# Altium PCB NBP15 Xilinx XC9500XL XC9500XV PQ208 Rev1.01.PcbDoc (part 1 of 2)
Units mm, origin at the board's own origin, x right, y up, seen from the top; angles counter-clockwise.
Board outline 69 x 80.99 mm, 2 copper layers (Top Layer, Bottom Layer); 37 components, 186 nets, 485 pads, 89 vias.
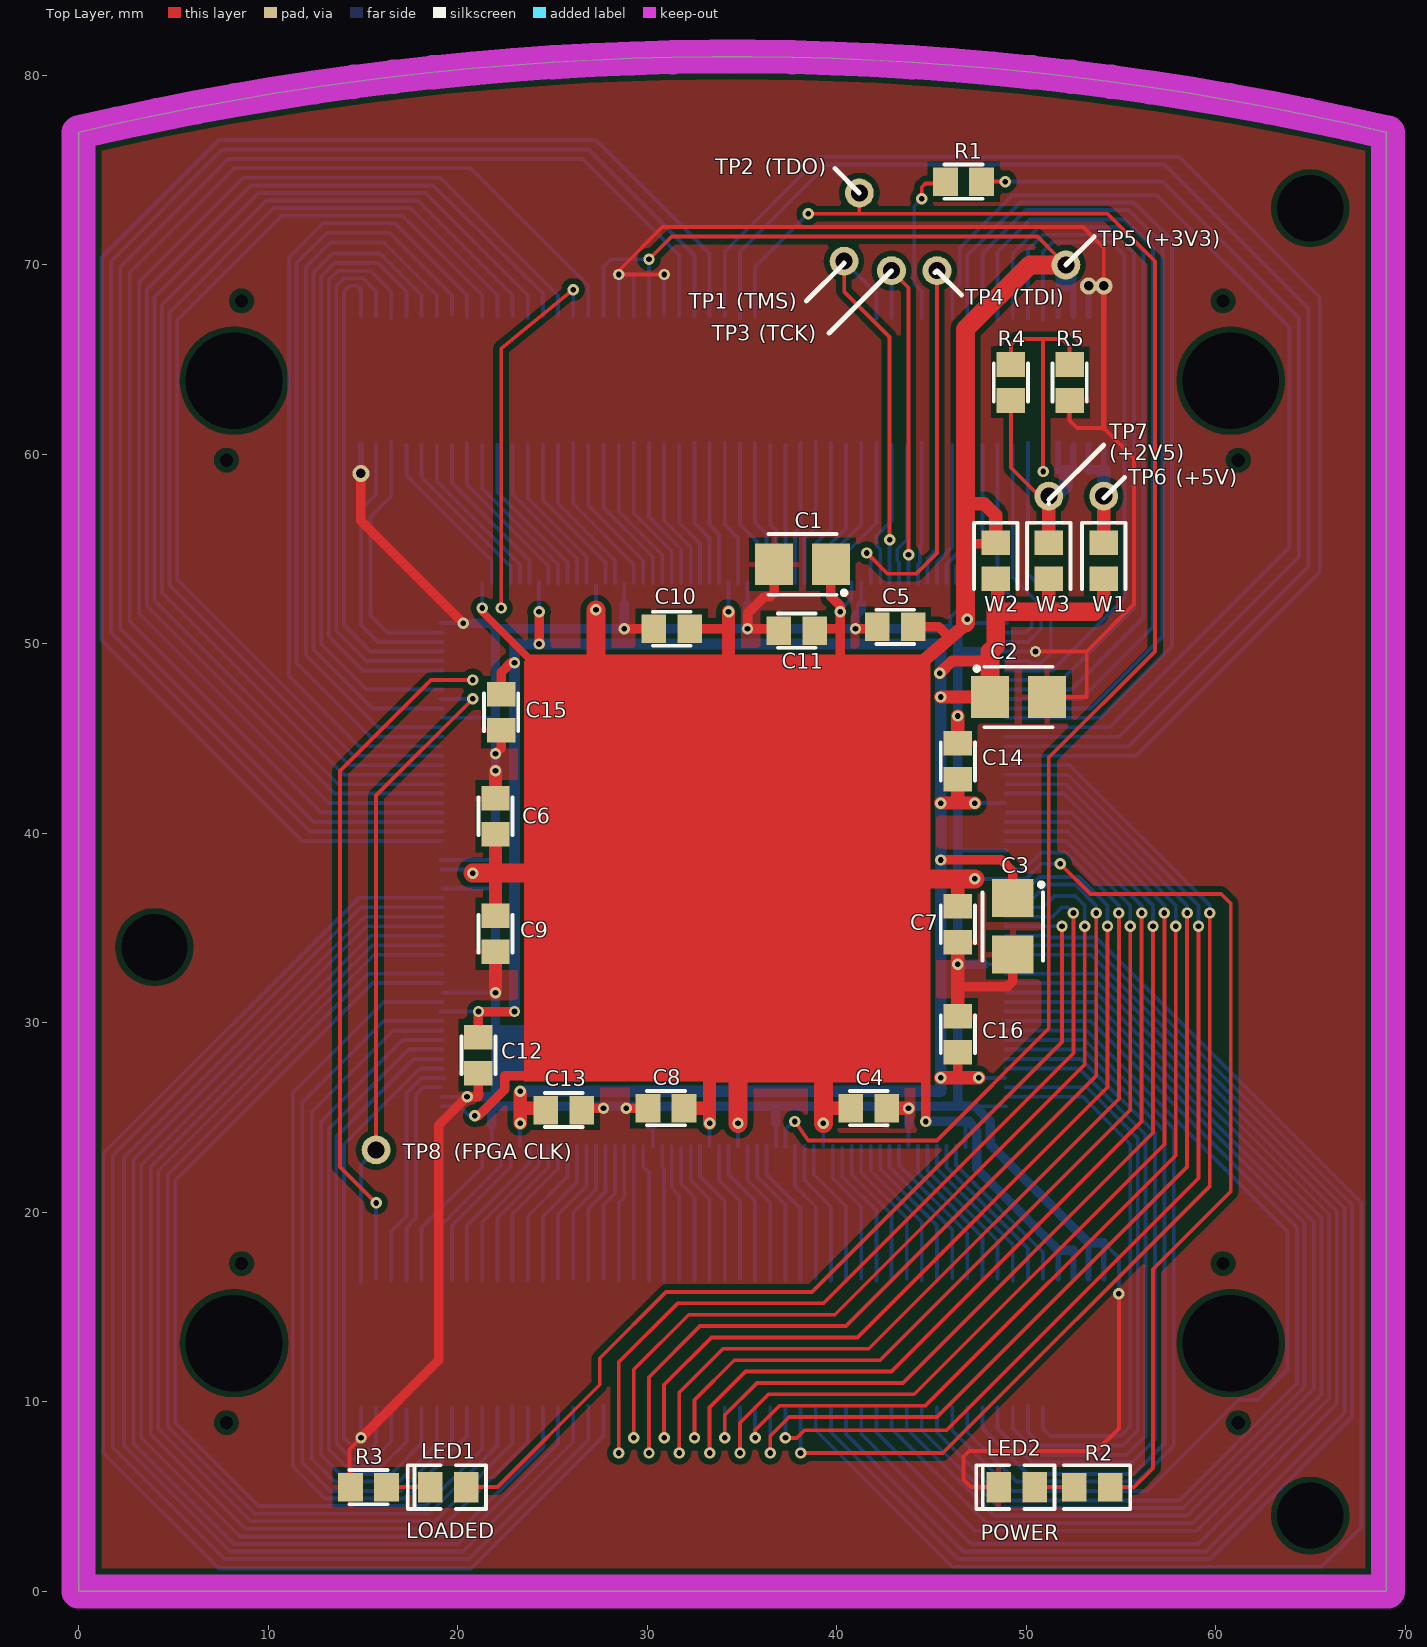
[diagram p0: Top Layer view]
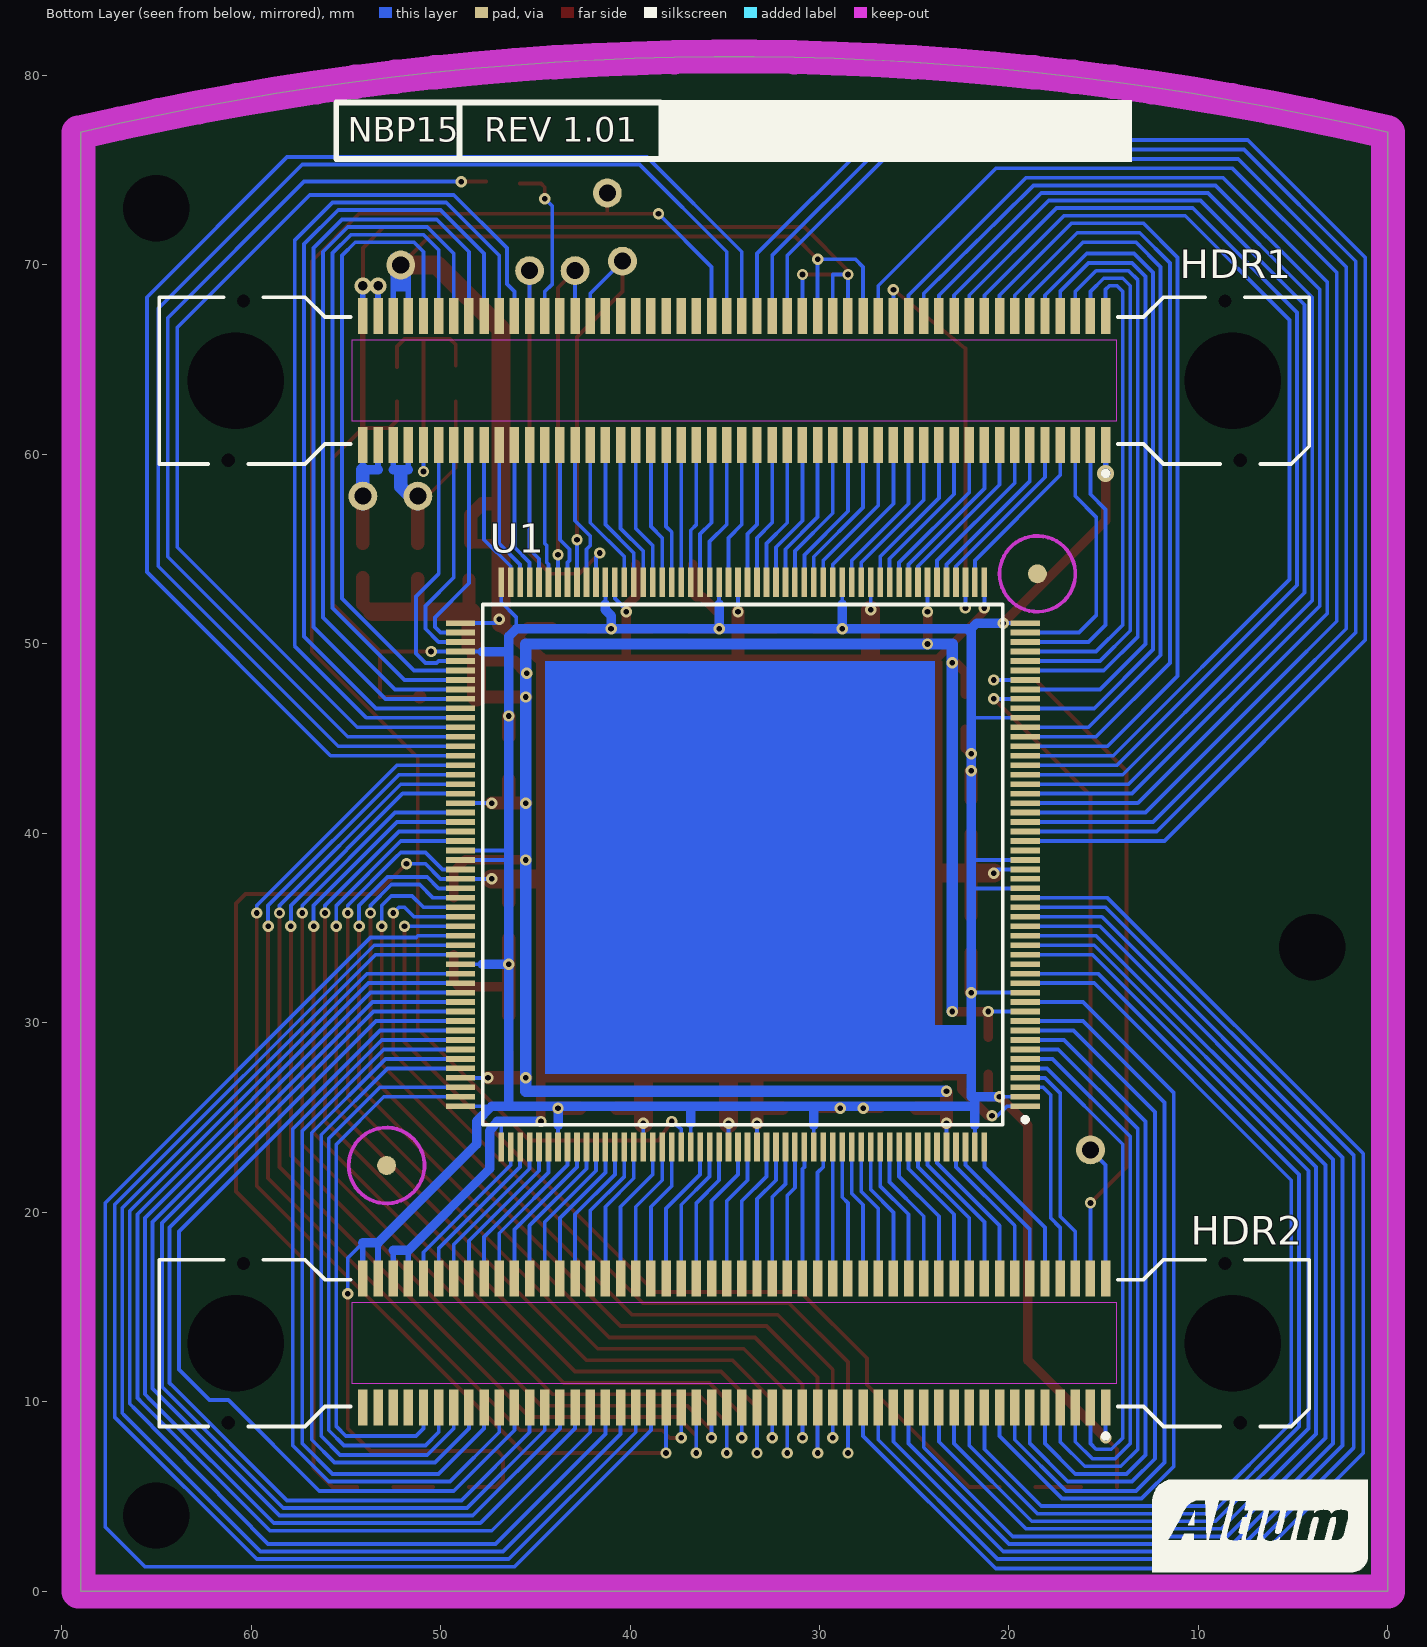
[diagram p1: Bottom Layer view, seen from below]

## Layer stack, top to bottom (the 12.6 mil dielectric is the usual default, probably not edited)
Top Layer: signal copper 0.0356
Dielectric: core 0.32, FR-4, Dk 4.8
Bottom Layer: signal copper 0.0356

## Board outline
0,0 0.001,77 cw(c34.5,-69.801) 69,77 69,0

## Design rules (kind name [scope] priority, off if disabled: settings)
AcuteAngle [All] p1 off: minimum=4.50000000000000E+0001
Clearance Clearance_Polygons [InPolygon] p1: gap=0.3
Clearance [All] p2: gap=0.2
ComponentClearance [All] p1: gap=0.2 collisioncheckmode=3 verticalgap=0.254 showdistances=FALSE
FabricationTestPointUsage TestPointUsage [All] p1 off: valid=0 allowmultiple=FALSE
FabricationTestpoint Testpoint [All] p1 off: side=3 testpointundercomponent=TRUE minsize=1.016 maxsize=2.54 preferedsize=1.524 minholesize=0 maxholesize=1.016 preferedholesize=0.813 testpointgrid=0.025 allowsidetop=TRUE allowsidebottom=TRUE usegrid=TRUE gridtolerance=0
HoleSize [All] p1: absolutevalues=TRUE maxlimit=5.2 minlimit=0.25 maxpercent=80.000 minpercent=20.000
MaximumViaCount [All] p1 off: limit=2
PlaneClearance [All] p1: clearance=0.45
PlaneConnect [All] p1: planeconnectstyle=Direct reliefexpansion=0.5 reliefentries=4 reliefconductorwidth=0.25 reliefairgap=0.25
PolygonConnect [All] p1: connectstyle=Relief reliefconductorwidth=0.3 reliefentries=4 polygonreliefangle="90 Angle"
RoomDefinition BOC_XC95288_PQ208 [InComponentClass('BOC_XC95288_PQ208')] p1 off: confinementstyle=ConfineIn formatcopy=TRUE lockcomponents=FALSE outline 3.6,3.7 65.2,3.7 65.2,75.8 3.6,75.8
RoutingVias [All] p1: holewidth=0.3 width=0.6 viastyle="Through Hole" minholewidth=0.3 minwidth=0.6 maxholewidth=0.5 maxwidth=1.4
SMDNeckDown [All] p1: percent=80.000
SilkscreenOverComponentPads [All] p1: minsilkscreentomaskgap=0.254
SolderMaskExpansion SolderMaskExpansion_Vias [IsVia] p1: expansion=-0.15
SolderMaskExpansion [All] p2: expansion=0.15
Width [All] p1: maxlimit=1.4 minlimit=0.2 preferedwidth=1 bottomlayer_prefwidth=0.2
21 further rules are at their usual default settings.

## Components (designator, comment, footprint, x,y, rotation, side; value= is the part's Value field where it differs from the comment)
C1 "10uF" MCCT-B 38.2,54.2 r180 top
C2 "10uF" MCCT-B 49.6,47.2 r0 top
C3 "10uF" MCCT-B 49.3,35.1 r270 top
C4 "0.1uF" CC2012-0805 41.7,25.5 r0 top
C5 "0.1uF" CC2012-0805 43.1,50.9 r180 top
C6 "0.1uF" CC2012-0805 22,40.9 r90 top
C7 "0.1uF" CC2012-0805 46.4,35.2 r270 top
C8 "0.1uF" CC2012-0805 31,25.5 r180 top
C9 "0.1uF" CC2012-0805 22,34.7 r270 top
C10 "0.1uF" CC2012-0805 31.3,50.8 r180 top
C11 "0.1uF" CC2012-0805 37.9,50.7 r180 top
C12 "0.1uF" CC2012-0805 21.1,28.3 r270 top
C13 "0.1uF" CC2012-0805 25.6,25.4 r0 top
C14 "0.1uF" CC2012-0805 46.4,43.8 r90 top
C15 "0.1uF" CC2012-0805 22.3,46.4 r270 top
C16 "0.1uF" CC2012-0805 46.4,29.4 r90 top
HDR1 "54075-1009-HD1" 54075 34.5,63.9 r0 bottom locked
HDR2 "54075-1009-HD2" 54075 34.5,13.1 r0 bottom locked
LED1 "HSMG-C170" "SMD _LED" 19.5,5.5 r0 top locked
LED2 "HSMH-C170" "SMD _LED" 49.5,5.5 r0 top locked
R1 "100R" CC2012-0805 46.7,74.4 r0 top
R2 "270R" CC2012-0805 53.5,5.5 r180 top locked
R3 "270R" CC2012-0805 15.3,5.5 r0 top
R4 "82R/1%" CC2012-0805 49.2,63.8 r90 top
R5 "680R/1%" CC2012-0805 52.3,63.8 r270 top
TP1 "TestPin" TestPin 40.4,70.2 r90 top
TP2 "TestPin" TestPin 41.2,73.8 r90 top
TP3 "TestPin" TestPin 42.9,69.7 r90 top
TP4 "TestPin" TestPin 45.3,69.7 r90 top
TP5 "TestPin" TestPin 52.1,70 r90 top
TP6 "TestPin" TestPin 54.1,57.8 r90 top
TP7 "TestPin" TestPin 51.2,57.8 r90 top
TP8 "TestPin" TestPin 15.7,23.3 r90 top
U1 "XC95288XL-10PQ208C" PQ208 34.05,38.35 r0 bottom locked
W1 "Jumper" CC2012-0805 54.1,54.4 r270 top
W2 "Jumper" CC2012-0805 48.4,54.4 r270 top
W3 "Jumper" CC2012-0805 51.2,54.4 r270 top

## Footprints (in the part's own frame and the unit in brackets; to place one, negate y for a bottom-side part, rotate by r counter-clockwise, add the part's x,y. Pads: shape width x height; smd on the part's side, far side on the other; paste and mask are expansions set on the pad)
54075 [mm] "Connector; Docking Station, Receptacle; 100 Position; Vertical"
  rect 0.5x1.9 smd: 1(-19.6,3.4) 2(-19.6,-3.4) 3(-18.8,3.4) 4(-18.8,-3.4) 5(-18,3.4) 6(-18,-3.4) 7(-17.2,3.4) 8(-17.2,-3.4) 9(-16.4,3.4) 10(-16.4,-3.4) 11(-15.6,3.4) 12(-15.6,-3.4) 13(-14.8,3.4) 14(-14.8,-3.4) 15(-14,3.4) 16(-14,-3.4) 17(-13.2,3.4) 18(-13.2,-3.4) 19(-12.4,3.4) 20(-12.4,-3.4) 21(-11.6,3.4) 22(-11.6,-3.4) 23(-10.8,3.4) 24(-10.8,-3.4) 25(-10,3.4) 26(-10,-3.4) 27(-9.2,3.4) 28(-9.2,-3.4) 29(-8.4,3.4) 30(-8.4,-3.4) 31(-7.6,3.4) 32(-7.6,-3.4) 33(-6.8,3.4) 34(-6.8,-3.4) 35(-6,3.4) 36(-6,-3.4) 37(-5.2,3.4) 38(-5.2,-3.4) 39(-4.4,3.4) 40(-4.4,-3.4) 41(-3.6,3.4) 42(-3.6,-3.4) 43(-2.8,3.4) 44(-2.8,-3.4) 45(-2,3.4) 46(-2,-3.4) 47(-1.2,3.4) 48(-1.2,-3.4) 49(-0.4,3.4) 50(-0.4,-3.4) 51(0.4,3.4) 52(0.4,-3.4) 53(1.2,3.4) 54(1.2,-3.4) 55(2,3.4) 56(2,-3.4) 57(2.8,3.4) 58(2.8,-3.4) 59(3.6,3.4) 60(3.6,-3.4) 61(4.4,3.4) 62(4.4,-3.4) 63(5.2,3.4) 64(5.2,-3.4) 65(6,3.4) 66(6,-3.4) 67(6.8,3.4) 68(6.8,-3.4) 69(7.6,3.4) 70(7.6,-3.4) 71(8.4,3.4) 72(8.4,-3.4) 73(9.2,3.4) 74(9.2,-3.4) 75(10,3.4) 76(10,-3.4) 77(10.8,3.4) 78(10.8,-3.4) 79(11.6,3.4) 80(11.6,-3.4) 81(12.4,3.4) 82(12.4,-3.4) 83(13.2,3.4) 84(13.2,-3.4) 85(14,3.4) 86(14,-3.4) 87(14.8,3.4) 88(14.8,-3.4) 89(15.6,3.4) 90(15.6,-3.4) 91(16.4,3.4) 92(16.4,-3.4) 93(17.2,3.4) 94(17.2,-3.4) 95(18,3.4) 96(18,-3.4) 97(18.8,3.4) 98(18.8,-3.4) 99(19.6,3.4) 100(19.6,-3.4)
  round 0.5 hole 0.7 unplated: MH1(-26.7,4.2) MH2(-25.9,-4.2) MH3(26.7,4.2) MH4(25.9,-4.2)
  round 4.8 hole 5.1 unplated: MH5(-26.3,0) MH6(26.3,0)
  Top Layer keep-out region: -20.15,2.15 20.15,2.15 20.15,-2.15 -20.15,-2.15
  silkscreen extent -30.35,-4.4 30.35,5.02
CC2012-0805 [mm]
  rect 1.3x1.5 smd: 1(-0.95,0) 2(0.95,0)
  silkscreen extent -1,-0.9 1,0.9
MCCT-B [mm]
  rect 2x2.2 smd: 1(-1.5,0) 2(1.5,0)
  silkscreen extent -2.3,-1.6 1.8,1.6
PQ208 [mm] "208-Pin Plastic Quad Flat Pack (PQ208)"
  rect 1.55x0.3 smd: 1(-14.9,12.75) 2(-14.9,12.25) 3(-14.9,11.75) 4(-14.9,11.25) 5(-14.9,10.75) 6(-14.9,10.25) 7(-14.9,9.75) 8(-14.9,9.25) 9(-14.9,8.75) 10(-14.9,8.25) 11(-14.9,7.75) 12(-14.9,7.25) 13(-14.9,6.75) 14(-14.9,6.25) 15(-14.9,5.75) 16(-14.9,5.25) 17(-14.9,4.75) 18(-14.9,4.25) 19(-14.9,3.75) 20(-14.9,3.25) 21(-14.9,2.75) 22(-14.9,2.25) 23(-14.9,1.75) 24(-14.9,1.25) 25(-14.9,0.75) 26(-14.9,0.25) 27(-14.9,-0.25) 28(-14.9,-0.75) 29(-14.9,-1.25) 30(-14.9,-1.75) 31(-14.9,-2.25) 32(-14.9,-2.75) 33(-14.9,-3.25) 34(-14.9,-3.75) 35(-14.9,-4.25) 36(-14.9,-4.75) 37(-14.9,-5.25) 38(-14.9,-5.75) 39(-14.9,-6.25) 40(-14.9,-6.75) 41(-14.9,-7.25) 42(-14.9,-7.75) 43(-14.9,-8.25) 44(-14.9,-8.75) 45(-14.9,-9.25) 46(-14.9,-9.75) 47(-14.9,-10.25) 48(-14.9,-10.75) 49(-14.9,-11.25) 50(-14.9,-11.75) 51(-14.9,-12.25) 52(-14.9,-12.75) 105(14.9,-12.75) 106(14.9,-12.25) 107(14.9,-11.75) 108(14.9,-11.25) 109(14.9,-10.75) 110(14.9,-10.25) 111(14.9,-9.75) 112(14.9,-9.25) 113(14.9,-8.75) 114(14.9,-8.25) 115(14.9,-7.75) 116(14.9,-7.25) 117(14.9,-6.75) 118(14.9,-6.25) 119(14.9,-5.75) 120(14.9,-5.25) 121(14.9,-4.75) 122(14.9,-4.25) 123(14.9,-3.75) 124(14.9,-3.25) 125(14.9,-2.75) 126(14.9,-2.25) 127(14.9,-1.75) 128(14.9,-1.25) 129(14.9,-0.75) 130(14.9,-0.25) 131(14.9,0.25) 132(14.9,0.75) 133(14.9,1.25) 134(14.9,1.75) 135(14.9,2.25) 136(14.9,2.75) 137(14.9,3.25) 138(14.9,3.75) 139(14.9,4.25) 140(14.9,4.75) 141(14.9,5.25) 142(14.9,5.75) 143(14.9,6.25) 144(14.9,6.75) 145(14.9,7.25) 146(14.9,7.75) 147(14.9,8.25) 148(14.9,8.75) 149(14.9,9.25) 150(14.9,9.75) 151(14.9,10.25) 152(14.9,10.75) 153(14.9,11.25) 154(14.9,11.75) 155(14.9,12.25) 156(14.9,12.75)
  rect 0.3x1.55 smd: 53(-12.75,-14.9) 54(-12.25,-14.9) 55(-11.75,-14.9) 56(-11.25,-14.9) 57(-10.75,-14.9) 58(-10.25,-14.9) 59(-9.75,-14.9) 60(-9.25,-14.9) 61(-8.75,-14.9) 62(-8.25,-14.9) 63(-7.75,-14.9) 64(-7.25,-14.9) 65(-6.75,-14.9) 66(-6.25,-14.9) 67(-5.75,-14.9) 68(-5.25,-14.9) 69(-4.75,-14.9) 70(-4.25,-14.9) 71(-3.75,-14.9) 72(-3.25,-14.9) 73(-2.75,-14.9) 74(-2.25,-14.9) 75(-1.75,-14.9) 76(-1.25,-14.9) 77(-0.75,-14.9) 78(-0.25,-14.9) 79(0.25,-14.9) 80(0.75,-14.9) 81(1.25,-14.9) 82(1.75,-14.9) 83(2.25,-14.9) 84(2.75,-14.9) 85(3.25,-14.9) 86(3.75,-14.9) 87(4.25,-14.9) 88(4.75,-14.9) 89(5.25,-14.9) 90(5.75,-14.9) 91(6.25,-14.9) 92(6.75,-14.9) 93(7.25,-14.9) 94(7.75,-14.9) 95(8.25,-14.9) 96(8.75,-14.9) 97(9.25,-14.9) 98(9.75,-14.9) 99(10.25,-14.9) 100(10.75,-14.9) 101(11.25,-14.9) 102(11.75,-14.9) 103(12.25,-14.9) 104(12.75,-14.9) 157(12.75,14.9) 158(12.25,14.9) 159(11.75,14.9) 160(11.25,14.9) 161(10.75,14.9) 162(10.25,14.9) 163(9.75,14.9) 164(9.25,14.9) 165(8.75,14.9) 166(8.25,14.9) 167(7.75,14.9) 168(7.25,14.9) 169(6.75,14.9) 170(6.25,14.9) 171(5.75,14.9) 172(5.25,14.9) 173(4.75,14.9) 174(4.25,14.9) 175(3.75,14.9) 176(3.25,14.9) 177(2.75,14.9) 178(2.25,14.9) 179(1.75,14.9) 180(1.25,14.9) 181(0.75,14.9) 182(0.25,14.9) 183(-0.25,14.9) 184(-0.75,14.9) 185(-1.25,14.9) 186(-1.75,14.9) 187(-2.25,14.9) 188(-2.75,14.9) 189(-3.25,14.9) 190(-3.75,14.9) 191(-4.25,14.9) 192(-4.75,14.9) 193(-5.25,14.9) 194(-5.75,14.9) 195(-6.25,14.9) 196(-6.75,14.9) 197(-7.25,14.9) 198(-7.75,14.9) 199(-8.25,14.9) 200(-8.75,14.9) 201(-9.25,14.9) 202(-9.75,14.9) 203(-10.25,14.9) 204(-10.75,14.9) 205(-11.25,14.9) 206(-11.75,14.9) 207(-12.25,14.9) 208(-12.75,14.9)
  silkscreen extent -15.02,-13.72 13.73,13.73
"SMD _LED" [mm]
  rect 1.3x1.6 smd: 1(0.95,0) 2(-0.95,0)
  silkscreen extent -2.13,-1.15 2,1.15
TestPin [mil] "SingleTest Pin"
  round 60 hole 35.43: 1(0,0)

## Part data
C1 C2 C3: library part CAP_POLAR, "Polar Capacitor"
C4 C5 C6 C7 C8 C9 C10 C11 C12 C13 C14 C15 C16: library part CAP, "Capacitor"
HDR1 HDR2: "Board-to-Board, Docking Station, 0.80mm (.031\") Pitch, Shielded Receptacle, Vertical, Ultra Low Profile, SMT"
LED1 LED2: library part HSMX-C670, "Typical RED GaAs SMD LED Agilent make"
R1 R2 R3 R4 R5: library part RES, "Resistor"
U1: "FastFLASH XC95288XL High Performance CPLD with 288 Macrocells, 208-Pin PQFP, Commercial Grade"
W1 W2 W3: "Jumper Wire"

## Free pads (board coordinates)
  round 1 smd far side mask+1.5: FD3(18.5,53.7) FD3(52.85,22.475)
  round 3.2 hole 3.5 unplated: LP(4,34) LP(65,4) LP(65,73)

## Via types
v1: diameter 0.6, hole 0.3, Top Layer to Bottom Layer, tented both sides, 86 vias
v2: diameter 0.9, hole 0.5, Top Layer to Bottom Layer, tented both sides, 3 vias

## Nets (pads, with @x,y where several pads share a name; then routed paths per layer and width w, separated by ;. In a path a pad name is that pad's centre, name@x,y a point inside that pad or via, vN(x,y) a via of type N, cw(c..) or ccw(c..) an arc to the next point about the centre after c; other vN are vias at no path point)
AUDIO_SPI_CSN: HDR1.11 U1.57 | length 9.1
  Bottom Layer w0.2: HDR1.11@18.9,60.5 18.9,58.6 23.3,54.2 U1.57@23.3,53.2
BLUE0: HDR1.14 U1.40 | length 41.6
  Bottom Layer w0.2: U1.40@19.2,45.1 15.4,45.1 11.5,49 11.5,70.1 13.1,71.7 16.4,71.7 19.7,68.4 HDR1.14@19.7,67.4
BLUE1: HDR1.16 U1.39 | length 44.5
  Bottom Layer w0.2: U1.39@19.1,44.6 14.8,44.6 11.1,48.3 11.1,70.4 12.9,72.2 16.7,72.2 20.5,68.4 HDR1.16@20.5,67.3
BOC_CTS: HDR1.13 U1.58 | length 9
  Bottom Layer w0.2: HDR1.13@19.7,60.5 19.7,58.5 23.8,54.4 U1.58@23.8,53.2
BOC_RTS: HDR1.17 U1.61 | length 9
  Bottom Layer w0.2: HDR1.17@21.3,60.5 21.3,58.2 25.3,54.2 U1.61@25.3,53.2
BOC_RX: HDR1.19 U1.62 | length 8.8
  Bottom Layer w0.2: HDR1.19@22.1,60.5 22.1,58 25.8,54.3 U1.62@25.8,53.2
BOC_TX: HDR1.15 U1.60 | length 9.2
  Bottom Layer w0.2: HDR1.15@20.5,60.6 HDR1.15@20.5,60.5 20.5,58.4 24.8,54.1 U1.60@24.8,53.2
BUZZER: HDR2.24 U1.199 | length 8
  Bottom Layer w0.2: HDR2.24@23.7,16.4 23.7,19.8 25.8,21.9 U1.199@25.8,23.5
CAN_RXD: HDR1.4 U1.48 | length 28.3
  Bottom Layer w0.2: HDR1.4@15.7,67.3 15.7,68.6 15,69.3 14,69.3 13.6,68.9 13.6,50.7 15.2,49.1 U1.48@19.2,49.1
CAN_TXD: HDR1.2 U1.49 | length 29.6
  Bottom Layer w0.2: HDR1.2@14.9,67.3 14.9,68.7 14.7,68.9 14.3,68.9 14,68.6 14,61.1 14,51 15.4,49.6 19.2,49.6 15.5,49.6
FPGA_AUX0: HDR1.86 U1.113 | length 42.4
  Bottom Layer w0.2: HDR1.86@48.5,67.1 48.5,70.7 50.2,72.4 55.2,72.4 56.7,70.9 56.7,50.9 52.9,47.1 U1.113@49,47.1
FPGA_AUX1: HDR1.88 U1.112 | length 39.6
  Bottom Layer w0.2: U1.112@48.9,47.6 52.4,47.6 56.2,51.4 56.2,70.7 54.9,72 50.7,72 49.3,70.6 HDR1.88@49.3,67.2
FPGA_AUX2: HDR1.90 U1.111 | length 37
  Bottom Layer w0.2: U1.111@48.9,48.1 51.9,48.1 55.7,51.9 55.7,70.634 54.734,71.6 50.9,71.6 50.1,70.8 HDR1.90@50.1,67.2
FPGA_AUX3: HDR1.92 U1.110 | length 34.4
  Bottom Layer w0.2: U1.110@48.9,48.6 51.4,48.6 55.2,52.4 55.2,70.5 54.5,71.2 51.4,71.2 50.9,70.7 HDR1.92@50.9,67.3 HDR1.92@50.9,67.1
FPGA_CCLK: HDR1.66
FPGA_CLK: HDR2.2 TP8.1 U1.44 | length 34.9
  Top Layer w0.2: TP8.1@15.7,23.3 15.7,42 v1(20.8,47.1)
  Bottom Layer w0.2: HDR2.2@14.9,16.3 14.9,22.5 TP8.1@15.7,23.3 ; U1.44@19.1,47.1 v1(20.8,47.1)
FPGA_CLK_1: HDR1.30 U1.55 | length 21.3
  Top Layer w0.2: v1(22.3,51.9) 22.3,65.6 v1(26.1,68.7)
  Bottom Layer w0.2: v1(22.3,51.9) U1.55@22.3,53.2 ; HDR1.30@26.1,67.3 v1(26.1,68.7)
FPGA_CLK_2: HDR1.32 U1.32 | length 69.7
  Bottom Layer w0.2: U1.32@19.2,41.1 12.8,41.1 5.8,48.1 2.7,51.2 2.7,58.5 2.7,69.6 8.2,75.1 19.6,75.1 20.7,75.1 26.9,68.9 HDR1.32@26.9,67.3
FPGA_DIN: HDR1.64
FPGA_DONE: HDR1.74
FPGA_INIT: HDR1.68
FPGA_M0: HDR1.60
FPGA_M1: HDR1.58
FPGA_M2: HDR1.56
FPGA_PROGRAM: HDR1.62
FPGA_TCK: HDR1.72 TP3.1 U1.98 | length 19.4
  Top Layer w0.2: TP3.1@42.9,69.7 43.8,68.8 v1(43.8,54.7)
  Bottom Layer w0.2: HDR1.72@42.9,67.2 TP3.1@42.9,69.7 ; U1.98@43.8,53.2 v1(43.8,54.7)
FPGA_TDI: HDR1.78 TP4.1 U1.94 | length 23.7
  Top Layer w0.2: v1(41.6,54.8) 42.7,53.7 44.2,53.7 45.3,54.8 TP4.1@45.3,69.7
  Bottom Layer w0.2: v1(41.6,54.8) 41.8,54.6 U1.94@41.8,53.2 ; HDR1.78@45.3,67.2 TP4.1@45.3,69.7
FPGA_TDO: HDR1.54 TP2.1 U1.176 | length 87.8
  Top Layer w0.2: v1(37.8,24.8) 38.5,23.8 45.3,23.8 51.2,29.7 51.2,44 56.8,49.6 56.8,70.2 54.3,72.7 v1(38.5,72.7) ; 41.2,72.7 TP2.1@41.2,73.8
  Bottom Layer w0.2: HDR1.54@35.7,67.3 35.7,69.9 v1(38.5,72.7) ; U1.176@37.3,23.45 37.3,24.4 v1(37.8,24.8)
FPGA_TMS: HDR1.70 TP1.1 U1.96 | length 21.7
  Top Layer w0.2: TP1.1@40.4,70.2 40.4,68.6 42.8,66.2 v1(42.8,55.5)
  Bottom Layer w0.2: TP1.1@40.4,70.2 42.1,68.5 HDR1.70@42.1,67.2 ; U1.96@42.8,53.2 v1(42.8,55.5)
GND: C1.2 C2.2 C3.2 C4.2 C5.2 C6.2 C7.2 C8.2 C9.2 C10.2 C11.2 C12.2 C13.2 C14.2 C15.2 C16.2 HDR1.1 HDR1.36 HDR1.38 HDR1.42 HDR1.98 HDR1.100 HDR2.1 HDR2.98 HDR2.100 LED2.2 R3.1 R5.2 U1.2 U1.13 U1.24 U1.27 U1.42 U1.52 U1.68 U1.81 U1.93 U1.104 U1.108 U1.129 U1.130 U1.141 U1.156 U1.163 U1.177 U1.190 U1.207 | length 325.4
  Top Layer w0.2: R3.1@14.3,5.5 14.3,7.5 v1(14.9,8.1) ; v1(30.9,69.5) v1(28.5,69.5) 28.5,69.7 30.8,72 31.1,72 ; 31,72 53,72 54.1,70.9 v2(54.1,68.9) ; LED2.2@48.5,5.5 47.1,5.5 46.7,5.9 46.7,7.1 47,7.4 53.7,7.4 54.9,8.6 v1(54.9,15.7) ; v1(50.5,49.6) 53.2,49.6 ; C2.2@51.1,47.2 53.2,47.2 53.2,49.6 ; R5.2@52.3,62.8 52.3,61.8 52.7,61.4 54.1,61.4 55.7,59.8 55.7,52.1 53.2,49.6
  Top Layer w0.3: 54.1,61.4 v2(54.1,68.9)
  Top Layer w0.5: v1(14.9,8.1) 19,12.2 19,24.6 v1(20.5,26.1) 21.1,26.1 C12.2@21.1,27.3 ; v2@14.9,59.1 14.9,56.5 v1(20.3,51.1) ; v1(22,44.2) 22.3,44.5 C15.2@22.3,45.5 ; C13.2@26.8,25.5 v1(27.7,25.5) ; v1(28.8,50.8) C10.2@30.3,50.8 ; v1(28.9,25.5) C8.2@30,25.5 ; C1.2@36.7,54.2 36.7,52.7 36.5,52.5 36.2,52.5 35.3,51.6 v1(35.3,50.8) C11.2@36.9,50.8 ; v1(41,50.8) C5.2@42.2,50.8 ; 46.4,31.9 49,31.9 49.3,32.2 C3.2@49.3,33.6
  Top Layer w0.7: v1(22,31.6) C9.2@22,33.7 ; C6.2@22,41.8 v1(22,43.3) ; C4.2@42.65,25.5 v1(43.8,25.5) ; C16.2@46.4,30.4 C7.2@46.4,34.45 ; C14.2@46.4,45.1 v1(46.4,46.2)
  Bottom Layer w0.2: v1(14.9,8.1) HDR2.1@14.9,9.7 ; v2@14.9,59.1 HDR1.1@14.9,60.5 ; U1.27@19.1,38.6 U1.27@19.15,38.6 22,38.6 ; U1.52@19.1,51.1 v1(20.3,51.1) ; U1.2@19.15,26.1 v1@20.485,26.1 ; U1.13@19.2,31.6 v1(22,31.6) ; U1.24@19.2,37.1 22,37.1 ; U1.42@19.2,46.1 22,46.1 ; 21.7,51.1 21.865,50.935 ; U1.207@21.8,23.45 21.8,24.6 ; 21.8,25.5 21.8,26.1 ; HDR1.36@28.5,67.3 v1(28.5,69.5) 29.3,69.5 HDR1.38@29.3,67.3 ; 28.8,52.1 U1.68@28.8,53.2 ; U1.190@30.3,23.5 30.3,24.6 ; HDR1.42@30.9,67.4 v1(30.9,69.5) ; 35.3,52.1 U1.81@35.3,53.25 ; U1.177@36.8,23.5 36.8,24.6 ; 41.3,52 U1.93@41.3,53.25 ; U1.163@43.8,23.5 43.8,24.6 ; 46,50.9 46,51.4 46.8,52.2 46.8,53.2 U1.104@46.8,53.25 ; 46.4,38.6 U1.130@48.9,38.6 ; 46.4,39.1 U1.129@48.95,39.1 ; 47.4,25.6 U1.156@48.95,25.6 ; 47.8,33.1 U1.141@48.95,33.1 ; 47.8,49.6 U1.108@48.95,49.6 ; U1.108@48.9,49.6 v1(50.5,49.6) ; 54.1,18.4 54.9,17.6 v1(54.9,15.7)
  Bottom Layer w0.3: v2(14.9,59) HDR1.1@14.9,60.5 ; HDR2.98@53.3,16.5 53.3,18.4 ; HDR1.98@53.3,67.3 v2@53.3,68.8 ; HDR2.100@54.1,16.5 54.1,18.4 ; HDR1.100@54.1,67.3 v2(54.1,68.9)
  Bottom Layer w0.5: v1(20.3,51.1) 21.7,51.1 22.1,50.7 ; v1@20.485,26.1 v1(20.5,26.1) 21.8,26.1 ; 21.8,24.6 21.8,26.1 ; 21.8,25.6 46.4,25.6 ; 28.8,52.1 v1(28.8,50.8) ; 30.3,24.6 30.3,25.5 ; 35.3,52.1 v1(35.3,50.8) ; 36.8,24.7 36.8,25.5 ; 41.3,52.1 41.3,51.8 41,51.5 v1(41,50.8) ; 43.8,24.6 v1(43.8,25.5) ; v1(46.4,33.1) 47.8,33.1 ; 47.8,49.6 46.4,49.6 ; 54.1,18.4 53.3,18.4 48.1,23.6 48.1,24.8 47.3,25.6 46.4,25.6 ; 21.8,26.1 22,26.1 22,29.7 v1(22,31.6) 22,50.8 v1(28.8,50.8) ; v1(28.8,50.8) v1(35.3,50.8) ; v1(35.3,50.8) v1(41,50.8) ; v1(41,50.8) 46,50.8 46.4,50.4 46.4,50 46.4,49.6 ; 46.4,25.6 46.4,49.6
  other v2: 53.3,68.9
GREEN0: HDR1.10 U1.43 | length 36.1
  Bottom Layer w0.2: HDR1.10@18.1,67.3 18.1,68.4 15.9,70.6 13.4,70.6 12.4,69.6 12.4,49.7 15.5,46.6 U1.43@19.2,46.6
GREEN1: HDR1.12 U1.41 | length 39
  Bottom Layer w0.2: HDR1.12@18.9,67.3 18.9,68.4 16.1,71.2 13.3,71.2 12,69.9 12,49.4 15.8,45.6 U1.41@19.2,45.6
HDRIVE: HDR1.18 U1.38 | length 52.8
  Bottom Layer w0.2: U1.38@19.2,44.1 14.5,44.1 5.2,53.4 5.2,67.1 10.7,72.6 17.1,72.6 21.3,68.4 HDR1.18@21.3,67.3
IO0: HDR2.7 U1.7 | length 31.4
  Bottom Layer w0.2: HDR2.7@17.3,9.6 17.3,7.9 16,6.6 14.1,6.6 13.2,7.5 13.2,24.4 17.4,28.6 U1.7@19.2,28.6
IO1: HDR2.9 U1.8 | length 34.1
  Bottom Layer w0.2: HDR2.9@18.1,9.7 18.1,7.8 16.5,6.2 13.8,6.2 12.8,7.2 12.8,24.8 17.1,29.1 U1.8@19.2,29.1
IO2: HDR2.11 U1.9 | length 36.8
  Bottom Layer w0.2: HDR2.11@18.9,9.7 18.9,7.8 16.9,5.8 13.5,5.8 12.3,7 12.3,25.3 16.6,29.6 U1.9@19.2,29.6
IO3: HDR2.13 U1.10 | length 39.5
  Bottom Layer w0.2: U1.10@19.2,30.1 16.1,30.1 11.8,25.8 11.8,6.8 13.3,5.3 17,5.3 19.7,8 HDR2.13@19.7,9.7
IO4: HDR2.15 U1.12 | length 42.4
  Bottom Layer w0.2: U1.12@19.2,31.1 16.1,31.1 11.3,26.3 11.3,6.6 13,4.9 17.2,4.9 20.5,8.2 HDR2.15@20.5,9.7
IO5: HDR2.17 U1.14 | length 52.7
  Bottom Layer w0.2: U1.14@19.2,32.1 15.5,32.1 5.1,21.7 5.1,8.9 9.5,4.5 18.3,4.5 21.3,7.5 HDR2.17@21.3,9.7
IO6: HDR2.19 U1.15 | length 55
  Bottom Layer w0.2: U1.15@19.2,32.6 15.3,32.6 4.7,22 4.7,8.7 9.3,4.1 18.5,4.1 22.1,7.7 HDR2.19@22.1,9.7
IO7: HDR2.21 U1.17 | length 57.7
  Bottom Layer w0.2: U1.17@19.2,33.6 15.6,33.6 4.2,22.2 4.2,8.6 9.1,3.7 12.1,3.7 18.8,3.7 22.9,7.8 HDR2.21@22.9,9.8
IO8: HDR2.23 U1.18 | length 60
  Bottom Layer w0.2: U1.18@19.2,34.1 15.5,34.1 3.8,22.4 3.8,8.3 8.8,3.3 18.4,3.3 19.1,3.3 23.7,7.9 HDR2.23@23.7,9.7
IO9: HDR2.25 U1.19 | length 62.7
  Bottom Layer w0.2: U1.19@19.2,34.6 15.4,34.6 3.3,22.5 3.3,8.1 8.5,2.9 18.7,2.9 19.8,2.9 24.5,7.6 HDR2.25@24.5,9.7
IO10: HDR2.27 U1.20 | length 65.1
  Bottom Layer w0.2: U1.20@19.2,35.1 15.2,35.1 2.9,22.8 2.9,7.8 8.2,2.5 11.2,2.5 20,2.5 25.3,7.8 HDR2.27@25.3,9.7
IO11: HDR2.29 U1.21 | length 67.5
  Bottom Layer w0.2: U1.21@19.2,35.6 15.1,35.6 2.4,22.9 2.4,7.7 8,2.1 10.9,2.1 20.3,2.1 26.1,7.9 HDR2.29@26.1,9.7
IO12: HDR2.31 U1.22 | length 70.2
  Bottom Layer w0.2: U1.22@19.2,36.1 14.9,36.1 1.8,23 1.8,19.9 1.8,7.6 7.7,1.7 10.7,1.7 20.6,1.7 26.9,8 HDR2.31@26.9,9.8
IO13: HDR2.33 U1.23 | length 72.7
  Bottom Layer w0.2: U1.23@19.2,36.6 14.8,36.6 1.3,23.1 1.3,7.3 7.4,1.2 20.7,1.2 27.7,8.2 HDR2.33@27.7,9.8
IO14: HDR2.35 U1.136 | length 49.4
  Top Layer w0.2: v1(28.5,7.3) 28.5,12.1 31.6,15.2 39.3,15.2 52.5,28.4 v1(52.5,35.8)
  Bottom Layer w0.2: v1(28.5,7.3) HDR2.35@28.5,9.8 ; U1.136@48.9,35.6 51.4,35.6 51.9,36.1 52.2,36.1 v1(52.5,35.8)
IO15: HDR2.37 U1.135 | length 48.7
  Top Layer w0.2: v1(29.3,8.1) 29.3,11.7 32.2,14.6 39.9,14.6 53.1,27.8 v1(53.1,35.1)
  Bottom Layer w0.2: v1(29.3,8.1) HDR2.37@29.3,9.7 ; U1.135@48.95,36.1 50.9,36.1 51.5,36.7 52.6,36.7 53.1,36.2 v1(53.1,35.1)
IO16: HDR2.39 U1.134 | length 51.1
  Top Layer w0.2: v1(30.1,7.3) 30.1,11.3 32.8,14 40.5,14 53.7,27.2 v1(53.7,35.8)
  Bottom Layer w0.2: v1(30.1,7.3) HDR2.39@30.1,9.7 ; U1.134@48.9,36.6 50.4,36.6 51.1,37.3 52.6,37.3 53.7,36.2 v1(53.7,35.8)
IO17: HDR2.41 U1.133 | length 50.2
  Top Layer w0.2: v1(30.9,8.1) 30.9,10.9 33.4,13.4 41.1,13.4 54.3,26.6 v1(54.3,35.1)
  Bottom Layer w0.2: v1(30.9,8.1) HDR2.41@30.9,9.7 ; U1.133@48.9,37.1 50.1,37.1 50.7,37.7 52.8,37.7 54.3,36.2 v1(54.3,35.1)
IO18: HDR2.43 U1.131 | length 53
  Top Layer w0.2: v1(31.7,7.3) 31.7,10.5 34,12.8 41.7,12.8 54.9,26 v1(54.9,35.8)
  Bottom Layer w0.2: v1(31.7,7.3) HDR2.43@31.7,9.7 ; U1.131@48.9,38.1 49.9,38.1 50.8,39 52.1,39 52.4,38.7 54.9,36.2 v1(54.9,35.8)
IO19: HDR2.45 U1.128 | length 51.7
  Top Layer w0.2: v1(32.5,8.1) 32.5,10.1 34.6,12.2 42.3,12.2 55.5,25.4 v1(55.5,35.1)
  Bottom Layer w0.2: v1(32.5,8.1) HDR2.45@32.5,9.7 ; U1.128@48.9,39.6 52.1,39.6 55.5,36.2 v1(55.5,35.1)
IO20: HDR2.47 U1.127 | length 60.9
  Top Layer w0.2: v1(33.3,7.3) 33.3,9.7 35.2,11.6 42.9,11.6 ; 36.1,11.6 42.9,11.6 ; v1(56.1,35.8) 56.1,24.8 42.9,11.6
  Bottom Layer w0.2: v1(33.3,7.3) HDR2.47@33.3,9.7 ; U1.127@48.9,40.1 52.2,40.1 56.1,36.2 v1(56.1,35.8)
IO21: HDR2.49 U1.126 | length 53.2
  Top Layer w0.2: v1(34.1,8.1) 34.1,9.3 35.8,11 43.5,11 56.7,24.2 v1(56.7,35.1)
  Bottom Layer w0.2: v1(34.1,8.1) HDR2.49@34.1,9.7 ; U1.126@48.9,40.6 52.3,40.6 56.7,36.2 v1(56.7,35.1)
IO22: HDR2.51 U1.125 | length 55.4
  Top Layer w0.2: v1(34.9,7.3) 34.9,8.9 36.4,10.4 44.1,10.4 57.3,23.6 v1(57.3,35.8)
  Bottom Layer w0.2: v1(34.9,7.3) HDR2.51@34.9,9.7 ; U1.125@49,41.1 52.4,41.1 57.3,36.2 v1(57.3,35.8)
IO23: HDR2.53 U1.123 | length 54.8
  Top Layer w0.2: v1(35.7,8.1) 35.7,8.5 37,9.8 44.7,9.8 57.9,23 v1(57.9,35.1)
  Bottom Layer w0.2: v1(35.7,8.1) HDR2.53@35.7,9.7 ; U1.123@48.9,42.1 U1.123@48.95,42.1 U1.123@49,42.099 ; U1.123@49,42.1 52,42.1 57.9,36.2 v1(57.9,35.1)
IO24: HDR2.55 U1.122 | length 57.1
  Top Layer w0.2: v1(36.5,7.3) 36.5,8.2 37.5,9.2 45.3,9.2 58.5,22.4 v1(58.5,35.8)
  Bottom Layer w0.2: v1(36.5,7.3) HDR2.55@36.5,9.7 ; U1.122@49,42.6 52.1,42.6 58.5,36.2 v1(58.5,35.8)
IO25: HDR2.57 U1.121 | length 56.5
  Top Layer w0.2: v1@37.3,8.2 v1(37.3,8.1) 37.9,8.1 38.3,8.5 45.8,8.5 59.1,21.8 v1(59.1,35.1)
  Bottom Layer w0.2: v1(37.3,8.1) HDR2.57@37.3,9.6 ; U1.121@48.9,43.1 52.2,43.1 59.1,36.2 v1(59.1,35.1)
IO26: HDR2.59 U1.120 | length 58.6
  Top Layer w0.2: v1@38,7.3 45.6,7.3 59.7,21.4 v1(59.7,35.8)
  Bottom Layer w0.2: v1(38.1,7.3) HDR2.59@38.1,9.7 ; U1.120@48.95,43.6 52.3,43.6 59.7,36.2 v1(59.7,35.8)
IO27: HDR2.61 U1.138 | length 75.5
  Bottom Layer w0.2: HDR2.61@38.9,9.7 38.9,8.5 46.1,1.3 58.598,1.3 ; U1.138@48.9,34.6 51.2,34.6 51.3,34.5 53.7,34.5 67.7,20.5 67.7,19.6 67.7,9.754 ; 58.6,1.3 59.3,1.3 65.6,1.3 67.7,3.4 67.7,9.7
IO28: HDR2.63 U1.139 | length 69.9
  Bottom Layer w0.2: HDR2.63@39.7,9.7 39.7,8.4 46.4,1.7 59.7,1.7 67.2,9.2 67.2,20.4 53.5,34.1 U1.139@48.9,34.1
IO29: HDR2.65 U1.140 | length 67.6
  Bottom Layer w0.2: HDR2.65@40.5,9.7 40.5,8.3 46.7,2.1 59.5,2.1 66.7,9.3 66.8,9.4 66.8,19.6 66.8,20.234 53.434,33.6 U1.140@48.9,33.6
IO30: HDR2.67 U1.142 | length 65
  Bottom Layer w0.2: HDR2.67@41.3,9.8 HDR2.67@41.3,9.7 41.3,8.3 47.1,2.5 59.1,2.5 66.1,9.6 66.4,9.9 66.4,19.2 66.4,20.069 53.869,32.6 U1.142@48.9,32.6
IO31: HDR2.69 U1.143 | length 62.2
  Bottom Layer w0.2: HDR2.69@42.1,9.8 42.1,8.4 47.3,3.2 58.1,3.2 59,3.2 65.7,9.9 66,10.2 66,19.9 53.8,32.1 U1.143@48.9,32.1
IO32: HDR2.71 U1.144 | length 59.5
  Bottom Layer w0.2: HDR2.71@42.9,9.7 42.9,8.6 47.9,3.6 58.8,3.6 65.3,10.1 65.6,10.4 65.6,18.8 65.6,19.7 53.7,31.6 U1.144@49,31.6
IO33: HDR2.73 U1.145 | length 57.2
  Bottom Layer w0.2: HDR2.73@43.7,9.7 43.7,8.6 48.3,4 58.5,4 65.2,10.7 65.2,19.5 53.6,31.1 U1.145@48.9,31.1
IO34: HDR2.75 U1.146 | length 54.9
  Bottom Layer w0.2: HDR2.75@44.5,9.8 44.5,8.5 48.6,4.4 58.3,4.4 64.5,10.6 64.7,10.8 64.7,19.434 53.534,30.6 U1.146@48.9,30.6
IO35: HDR2.77 U1.147 | length 52.4
  Bottom Layer w0.2: HDR2.77@45.3,9.7 45.3,8.4 48.9,4.8 58.1,4.8 64.1,10.8 64.3,11 64.3,18.269 ; U1.147@48.9,30.1 53.4,30.1 64.3,19.2 64.3,18.3
JIOA0: HDR1.3 U1.50 | length 14.5
  Bottom Layer w0.2: HDR1.3@15.7,60.5 15.7,57.9 14.9,57.1 14.9,51 15.8,50.1 U1.50@19.2,50.1
JIOA1: HDR1.5 U1.51 | length 13.8
  Bottom Layer w0.2: HDR1.5@16.5,60.7 HDR1.5@16.5,60.5 16.5,57.8 15.4,56.7 15.4,51.5 16.3,50.6 U1.51@19.2,50.6
JIOA2: HDR1.7 U1.54 | length 9.2
  Bottom Layer w0.2: HDR1.7@17.3,60.5 17.3,58.9 21.8,54.4 U1.54@21.8,53.2
JIOA3: HDR1.9 U1.56 | length 9.2
  Bottom Layer w0.2: HDR1.9@18.1,60.5 18.1,58.8 22.8,54.1 U1.56@22.8,53.2
JIOB0: HDR1.83 U1.103 | length 7.9
  Bottom Layer w0.2: U1.103@46.3,53.2 46.3,54.1 47.7,55.5 HDR1.83@47.7,60.5
JIOB1: HDR1.85 U1.106 | length 11.9
  Bottom Layer w0.2: HDR1.85@48.5,60.5 48.5,53.2 50.3,51.4 50.3,50.9 50,50.6 U1.106@48.9,50.6
JIOB2: HDR1.87 U1.107 | length 12.5
  Bottom Layer w0.2: U1.107@48.9,50.1 50.1,50.1 50.8,50.8 50.8,52 49.3,53.5 HDR1.87@49.3,60.5
JIOB3: HDR1.89 U1.109 | length 14.2
  Bottom Layer w0.2: U1.109@48.9,49.1 50.1,49.1 50.2,49 50.8,49 51.3,49.5 51.3,52.5 50.1,53.7 HDR1.89@50.1,60.6
KBCLOCK: HDR1.22 U1.36 | length 57.9
  Bottom Layer w0.2: U1.36@19.2,43.1 14,43.1 7.5,49.6 4.4,52.7 4.4,67.9 9.9,73.4 17.9,73.4 22.9,68.4 HDR1.22@22.9,67.3
KBDATA: HDR1.24 U1.35 | length 60.6
  Bottom Layer w0.2: U1.35@19.2,42.6 13.7,42.6 4,52.3 4,68.3 9.5,73.8 18.3,73.8 23.7,68.4 HDR1.24@23.7,67.2
LCD_BCKL: HDR2.22 U1.200 | length 8.1
  Bottom Layer w0.2: HDR2.22@22.9,16.4 22.9,19.9 25.3,22.3 U1.200@25.3,23.5
LCD_E: HDR2.26 U1.198 | length 7.8
  Bottom Layer w0.2: HDR2.26@24.5,16.4 24.5,19.8 26.3,21.6 U1.198@26.3,23.5
LED0: HDR2.60 U1.178 | length 7.8
  Bottom Layer w0.2: U1.178@36.3,23.5 36.3,22 38.1,20.2 HDR2.60@38.1,16.4
LED1: HDR2.62 U1.175 | length 7.5
  Bottom Layer w0.2: U1.175@37.8,23.5 37.8,21.4 38.9,20.3 HDR2.62@38.9,16.5
LED2: HDR2.64 U1.174 | length 7.7
  Bottom Layer w0.2: U1.174@38.3,23.5 38.3,21.7 39.7,20.3 HDR2.64@39.7,16.4
LED3: HDR2.66 U1.173 | length 7.8
  Bottom Layer w0.2: U1.173@38.8,23.5 38.8,22 40.5,20.3 HDR2.66@40.5,16.4
LED4: HDR2.68 U1.171 | length 7.6
  Bottom Layer w0.2: U1.171@39.8,23.5 39.8,21.8 41.3,20.3 HDR2.68@41.3,16.5
LED5: HDR2.70 U1.170 | length 7.7
  Bottom Layer w0.2: U1.170@40.3,23.4 40.3,21.9 42.1,20.1 HDR2.70@42.1,16.5 HDR2.70@42.1,16.4
LED6: HDR2.72 U1.169 | length 8
  Bottom Layer w0.2: U1.169@40.8,23.5 40.8,22 42.9,19.9 HDR2.72@42.9,16.5 HDR2.72@42.9,16.4
LED7: HDR2.74 U1.168 | length 8
  Bottom Layer w0.2: U1.168@41.3,23.5 41.3,22.1 43.7,19.7 HDR2.74@43.7,16.5
MOUSECLOCK: HDR1.26 U1.34 | length 63.1
  Bottom Layer w0.2: U1.34@19.2,42.1 13.5,42.1 3.6,52 3.6,68.7 9.1,74.2 18.7,74.2 24.5,68.5 HDR1.26@24.5,67.3
MOUSEDATA: HDR1.28 U1.33 | length 65.7
  Bottom Layer w0.2: U1.33@19.2,41.6 13.2,41.6 3.2,51.6 3.2,69.1 8.7,74.6 19.1,74.6 25.3,68.4 HDR1.28@25.3,67.3
NetLED1_2: LED1.2 R3.2 | length 2.4
  Top Layer w0.2: R3.2@16.2,5.5 LED1.2@18.6,5.5
NetLED2_1: LED2.1 R2.2 | length 2.1
  Top Layer w0.2: LED2.1@50.4,5.5 R2.2@52.5,5.5
NEXUS_TCK: HDR1.82 U1.115 | length 47.8
  Bottom Layer w0.2: HDR1.82@46.9,67.2 46.9,70.5 49.7,73.3 55.7,73.3 57.7,71.3 57.7,49.9 53.9,46.1 U1.115@48.95,46.1
NEXUS_TDI: HDR1.84 U1.114 | length 45.1
  Bottom Layer w0.2: HDR1.84@47.7,67.2 47.7,70.6 50,72.9 55.4,72.9 57.2,71.1 57.2,50.4 53.4,46.6 U1.114@49,46.6
NEXUS_TDO: R1.2 U1.117 | length 51.8
  Top Layer w0.2: R1.2@47.6,74.4 v1(48.9,74.4)
  Bottom Layer w0.2: U1.117@48.9,45.1 54.9,45.1 64.4,54.6 64.4,67.2 57.2,74.4 v1(48.9,74.4)
NEXUS_TDO#: HDR1.76 R1.1 | length 8.6
  Top Layer w0.2: v1(44.5,73.5) 44.5,74.1 44.7,74.3 R1.1@45.8,74.3
  Bottom Layer w0.2: HDR1.76@44.5,67.2 HDR1.76@44.5,67.3 44.5,68.6 44.1,69 44.1,73.1 v1(44.5,73.5)
NEXUS_TMS: HDR1.80 U1.116 | length 55.9
  Bottom Layer w0.2: HDR1.80@46.1,67.2 HDR1.80@46.1,67.3 46.1,68.6 46.5,69 46.5,70.9 49.3,73.7 49.8,73.7 56.9,73.7 63.9,66.7 63.9,55.1 54.4,45.6 U1.116@48.9,45.6
PROGRAMMED: LED1.1 U1.137 | length 51.2
  Top Layer w0.2: LED1.1@20.5,5.5 22.1,5.5 27.5,10.9 27.5,12.3 31,15.8 38.7,15.8 51.9,29 v1(51.9,35.1)
  Bottom Layer w0.2: U1.137@48.9,35.1 v1@52,35.1
RAM0_DATA0: HDR2.42 U1.189 | length 7.1
  Bottom Layer w0.2: U1.189@30.8,23.5 30.8,22.4 30.9,22.3 HDR2.42@30.9,16.5 HDR2.42@30.9,16.4
RAM0_DATA1: HDR2.40 U1.191 | length 7.2
  Bottom Layer w0.2: U1.191@29.8,23.5 29.8,22.4 30.1,22.1 HDR2.40@30.1,16.4
RAM0_DATA2: HDR2.38 U1.192 | length 7
  Bottom Layer w0.2: HDR2.38@29.3,16.5 U1.192@29.3,23.5
RAM0_DATA3: HDR2.36 U1.193 | length 7.2
  Bottom Layer w0.2: HDR2.36@28.5,16.4 HDR2.36@28.5,16.5 28.5,20.5 28.8,20.8 U1.193@28.8,23.5
RAM0_DATA4: HDR2.34 U1.194 | length 7.2
  Bottom Layer w0.2: HDR2.34@27.7,16.5 27.7,20.4 28.3,21 U1.194@28.3,23.5
RAM0_DATA5: HDR2.32 U1.195 | length 7.5
  Bottom Layer w0.2: HDR2.32@26.9,16.4 26.9,20.2 27.8,21.1 U1.195@27.8,23.5
RAM0_DATA6: HDR2.30 U1.196 | length 7.5
  Bottom Layer w0.2: HDR2.30@26.1,16.5 26.1,20 27.3,21.2 U1.196@27.3,23.5
RAM0_DATA7: HDR2.28 U1.197 | length 7.6
  Bottom Layer w0.2: HDR2.28@25.3,16.5 25.3,19.9 26.8,21.4 U1.197@26.8,23.5
RAM0_OE: HDR1.41 U1.75 | length 7.9
  Bottom Layer w0.2: HDR1.41@30.9,60.5 30.9,56.5 32.3,55.1 U1.75@32.3,53.2
RAM0_WE: HDR1.79 U1.101 | length 7.6
  Bottom Layer w0.2: U1.101@45.3,53.2 45.3,54.3 46.1,55.1 HDR1.79@46.1,60.5
RAM1_DATA0: HDR1.45 U1.77 | length 7.7
  Bottom Layer w0.2: HDR1.45@32.5,60.6 HDR1.45@32.5,60.5 32.5,56.4 33.3,55.6 U1.77@33.3,53.2
RAM1_DATA1: HDR1.49 U1.80 | length 7.7
  Bottom Layer w0.2: HDR1.49@34.1,60.6 HDR1.49@34.1,60.5 34.1,56.3 34.8,55.6 U1.80@34.8,53.2
RAM1_DATA2: HDR1.53 U1.83 | length 7.6
  Bottom Layer w0.2: HDR1.53@35.7,60.6 35.7,56.4 36.3,55.8 U1.83@36.3,53.2
RAM1_DATA3: HDR1.57 U1.85 | length 13.5
  Bottom Layer w0.2: U1.85@37.3,53.2 HDR1.57@37.3,60.5 37.3,54.3
RAM1_DATA4: HDR1.55 U1.84 | length 7.4
  Bottom Layer w0.2: HDR1.55@36.5,60.5 36.5,56.3 36.8,56 U1.84@36.8,53.2
RAM1_DATA5: HDR1.51 U1.82 | length 7.8
  Bottom Layer w0.2: HDR1.51@34.9,60.6 34.9,56.3 35.8,55.4 U1.82@35.8,53.2
RAM1_DATA6: HDR1.47 U1.78 | length 7.6
  Bottom Layer w0.2: HDR1.47@33.3,60.6 HDR1.47@33.3,60.5 33.3,56.3 33.8,55.8 U1.78@33.8,53.2
RAM1_DATA7: HDR1.43 U1.76 | length 7.8
  Bottom Layer w0.2: HDR1.43@31.7,60.5 31.7,56.4 32.8,55.3 U1.76@32.8,53.2
RAM1_OE: HDR1.39 U1.74 | length 8.1
  Bottom Layer w0.2: HDR1.39@30.1,60.6 HDR1.39@30.1,60.5 30.1,56.7 31.8,55 U1.74@31.8,53.2
RAM1_WE: HDR1.61 U1.87 | length 7.7
  Bottom Layer w0.2: U1.87@38.3,53.2 38.3,55.6 38.9,56.2 HDR1.61@38.9,60.5 HDR1.61@38.9,60.7
RAM_ADDR0: HDR1.21 U1.63 | length 8.7
  Bottom Layer w0.2: HDR1.21@22.9,60.5 22.9,57.9 26.3,54.5 U1.63@26.3,53.2
RAM_ADDR1: HDR1.25 U1.66 | length 8.7
  Bottom Layer w0.2: HDR1.25@24.5,60.5 24.5,57.6 27.8,54.3 U1.66@27.8,53.2
RAM_ADDR2: HDR1.29 U1.69 | length 8.7
  Bottom Layer w0.2: HDR1.29@26.1,60.6 26.1,57.4 29.3,54.2 U1.69@29.3,53.2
